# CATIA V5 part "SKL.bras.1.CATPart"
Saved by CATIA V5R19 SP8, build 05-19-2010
Part number: SKL.bras.1
Bounding box of the stored display mesh (mm): x -6.997 to 12, y -67.5 to 20.337, z -29.757 to -2.883
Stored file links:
  G:\EU_thinkMotion\CFAO_2010\MMS_groupe3\MMS_groupe3\jbonnamy\jbonnamy_cfao\SKL.bras.1.CATPart
  G:\EU_thinkMotion\CFAO_2010\MMS_groupe3\MMS_groupe3\jbonnamy\jbonnamy_cfao\jbonnamy_suspension.arriere.directionnelle.CATProduct
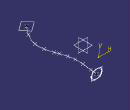
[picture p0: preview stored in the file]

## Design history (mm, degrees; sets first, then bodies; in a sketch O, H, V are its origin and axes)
External parameters (linked from other documents)
  External.Diametre.tube.ext = 14 mm
  External.Diametre.tube.int = 12 mm
Body1 (main body)
  Point1: (5, -67.5, -10)
  Point2: (10, -60, -13)
  Point3: (12, -50, -17.5)
  Point4: (10, -40, -19)
  Point5: (7, -30, -19.5)
  Point6: (5, -25, -19.5)
  Point7: (2, -17.5, -20)
  Point8: (0, 0, -21)
  Point9: (0, 10, -22)
  Point10: (0, 17.5, -23)
  Point11 "Point.8": (0, -10, -20.5)
  Curve1 "Spline.bras.suspension": Elements (Point1; Point2; Point3; Point4; Point5; Point6; Point7; Point11; Point8; Point9; Point10)
  Plane1: type Normal, Curve Curve1, RefPoint Point10
  Sketch1 "Esquisse.tube.bras.suspension.ext" on Plane1, origin (0.5493, 20.3368, -2.8828), H (-0.9996, 0.027, 0), V (0.0038, 0.1402, 0.9901)
    circle A1 centre (0.4725, -20.3182) radius 7
    point P1 (0.4725, -20.3182)
    reference projected point E1 (0.4725, -20.3182) from Point10
    radius A1 = 7 {= External.Diametre.tube.ext /2}
    distance P1 E1 = 0
  Plane2: type Normal, Curve Curve1, RefPoint Point1
  Sketch2 "Esquisse.tube.bras.suspension.int" on Plane1, origin (0.5493, 20.3368, -2.8828), H (-0.9996, 0.027, 0), V (0.0038, 0.1402, 0.9901)
    circle A1 centre (0.4725, -20.3182) radius 6
    point P1 (0.4725, -20.3182)
    reference projected point E1 (0.4725, -20.3182) from Point10
    radius A1 = 6 {= External.Diametre.tube.int /2}
    distance P1 E1 = 0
